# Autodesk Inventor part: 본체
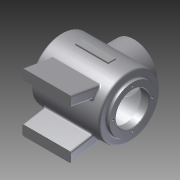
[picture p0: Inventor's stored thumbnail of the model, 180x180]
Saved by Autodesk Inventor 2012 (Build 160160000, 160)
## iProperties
Created: 2015-01
Part Number: 본체
Material: Default
Document SubType Name: Modeling
Designer: Class3-User
Density: 1 g/cm^3
Author: Class3-User
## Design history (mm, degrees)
sketch "스케치1"
  geometry: 1 further point
sketch "스케치2"
  geometry: C1 r 50 at (0, 0); 1 further point
  constraints: 1 centre point, 1 coincident
  dimensions: "d0" = 100 diameter of C1
extrude "돌출1" new body sketch "스케치2" distance "d1" = 112; taper "d2" = 0 deg
sketch "스케치3"
  geometry: C1 r 50 at (0, 0) reference; C2 r 38 at (0, 0)
  constraints: 1 centre point, 1 coincident
  dimensions: "d3" = 76 diameter of C2
extrude "돌출2" join sketch "스케치3" distance "d4" = 5; taper "d5" = 0 deg
sketch "스케치4"
  geometry: C1 r 50 at (0, 0) reference; C2 r 38 at (0, 0)
  constraints: 1 centre point, 1 coincident
  dimensions: "d6" = 76 diameter of C2
extrude "돌출3" join sketch "스케치4" distance "d7" = 5; taper "d8" = 0 deg
node "작업 평면1"
sketch "스케치5"
  geometry: L1 (0, 0)-(5, 0); L2 (5, 0)-(-57, 0); C1 r 38 at (-57, 0)
  constraints: 4 end point, 1 centre point, 1 coincident, 1 collinear, 1 horizontal
  dimensions: "d10" = 5 distance of L1.start L1.end; "d11" = 62 distance of L1.end L2.end; "d12" = 76 diameter of C1
extrude "돌출4" join sketch "스케치5" distance "d13" = 50; taper "d14" = 0 deg
sketch "스케치6"
  geometry: C1 r 38 at (0, 0) reference; C2 r 27 at (0, 0)
  constraints: 1 centre point, 1 coincident
  dimensions: "d15" = 54 diameter of C2
extrude "돌출5" cut sketch "스케치6" stored distance "d16" = 99; taper "d17" = 0 deg
node "작업 평면2"
sketch "스케치7"
  geometry: C1 r 45 at (0, 0); 1 further point
  constraints: 1 centre point, 1 coincident
  dimensions: "d19" = 90 diameter of C1
extrude "돌출6" cut sketch "스케치7" distance "d20" = 97; taper "d21" = 0 deg
sketch "스케치8"
  geometry: C1 r 38 at (0, 0) reference; C2 r 27 at (0, 0); 1 further point
  constraints: 1 centre point, 1 coincident
  dimensions: "d22" = 54 diameter of C2
extrude "돌출7" cut sketch "스케치8" distance "d23" = 50; taper "d24" = 0 deg
sketch "스케치9" dims "d25" = 64
  geometry: L1 (0, 32)-(0, 0); C1 r 38 at (0, 0) reference; C2 r 2 at (0, 32); 1 further point
  constraints: 2 end point, 1 centre point, 1 coincident, 1 vertical, 1 vertical alignment, 2 other
  dimensions: "d26" = 4 diameter of C2
hole "구멍1" sketch "스케치9" at (0, 32) diameter "d27" = 3.459; stored, may be unused: countersink angle "d31" = 82 deg, drill point angle "d33" = 118 deg; dims "d28" = 8, "d29" = 3.023, "d30" = 2, "d32" = 10
sketch "스케치10" dims "d37" = 64
  geometry: L1 (0, 0)-(0, 32); C1 r 38 at (0, 0) reference; C2 r 2 at (0, 32)
  constraints: 2 end point, 1 centre point, 1 coincident, 1 vertical, 1 vertical alignment, 2 other
  dimensions: "d38" = 4 diameter of C2
hole "구멍2" sketch "스케치10" at (0, 32) diameter "d39" = 3.459; stored, may be unused: countersink angle "d43" = 82 deg, drill point angle "d45" = 118 deg; dims "d40" = 8, "d41" = 3.023, "d42" = 2, "d44" = 10
sketch "스케치11" dims "d49" = 64
  geometry: L1 (0, 0)-(0, 32); C1 r 38 at (0, 0) reference; C2 r 2 at (0, 32)
  constraints: 2 end point, 1 centre point, 1 coincident, 1 vertical, 1 vertical alignment, 2 other
  dimensions: "d50" = 4 diameter of C2
hole "구멍3" sketch "스케치11" at (0, 32) diameter "d51" = 3.459; stored, may be unused: countersink angle "d55" = 82 deg, drill point angle "d57" = 118 deg; dims "d52" = 8, "d53" = 3.023, "d54" = 2, "d56" = 10
node "작업 평면3"
sketch "스케치12"
  geometry: L1 (0, 0)-(0, -80); L2 (0, -80)-(-48, -80); L3 (-48, -80)-(-38.973, -28.807) reference; L4 (-38.973, -28.807)-(-24.238, -39.957) reference; L5 (-24.238, -39.957)-(-31.298, -80) reference
  constraints: 10 end point, 1 parallel, 1 perpendicular, 1 point on line, 1 vertical, 3 other
  dimensions: "d62" = 80 distance of L1.start L1.end
extrude "돌출8" join sketch "스케치12" distance "d66" = 80; taper "d67" = 0 deg
fillet "모깎기1" dims "d68" = 3
fillet "모깎기2" dims "d69" = 3
chamfer "모따기1" distance "d70" = 1; stored, may be unused: second distance "d71" = 2, angle "d72" = 45 deg
fillet "모깎기3" dims "d73" = 3
fillet "모깎기4" dims "d74" = 3
sketch "스케치13"
  geometry: 1 further point
node "작업 평면4"
sketch "스케치14"
  geometry: L1 (0, 0)-(56, 0); L2 (56, 0)-(56, 6); L3 (56, 6)-(29, 6); L4 (29, 6)-(29, -6); L5 (29, -6)-(83, -6); L6 (83, -6)-(83, 6); L7 (83, 6)-(56, 6)
  constraints: 14 end point, 3 perpendicular, 2 parallel, 1 horizontal
  dimensions: "d76" = 56 distance of L1.start L1.end; "d77" = 6 distance of L1.end L2.end; "d78" = 27 distance of L2.end L3.end; "d79" = 12 distance of L3.end L4.end; "d80" = 54 distance of L4.end L5.end; "d81" = 12 distance of L5.end L6.end
extrude "돌출9" join sketch "스케치14" distance "d82" = 4; taper "d83" = 0 deg
sketch "스케치15"
  geometry: L1 (-52, 6)-(-52, -6) reference; L2 (-49.639, 6)-(-52, 6) reference; L3 (-52, -6)-(-49.639, -6) reference; C1 r 28 at (0, 0) reference; A1 r 50 centre (0, 0) between (-49.639, 6) and (-49.639, -6) reference
  constraints: 6 end point, 2 horizontal, 2 point on circle, 1 centre point, 1 coincident, 1 parallel, 1 vertical, 5 other
extrude "돌출10" cut sketch "스케치15" distance "d88" = 99; taper "d89" = 0 deg
node "작업 평면5"
sketch "스케치16"
  geometry: L1 (0, 0)-(56, 0); L2 (56, 0)-(56, -6); L3 (56, -6)-(29, -6); L4 (29, -6)-(29, 6); L5 (29, 6)-(83, 6); L6 (83, 6)-(83, -6); L7 (83, -6)-(56, -6)
  constraints: 14 end point, 3 perpendicular, 2 parallel, 1 horizontal
  dimensions: "d91" = 56 distance of L1.start L1.end; "d92" = 6 distance of L1.end L2.end; "d93" = 27 distance of L2.end L3.end; "d94" = 12 distance of L3.end L4.end; "d95" = 54 distance of L4.end L5.end; "d96" = 12 distance of L5.end L6.end
extrude "돌출11" join sketch "스케치16" distance "d97" = 4; taper "d98" = 0 deg
node "솔리드1"
pattern_circular "원형 패턴1" dims angle "d35" = 360 deg
pattern_circular "원형 패턴2" dims angle "d47" = 360 deg
pattern_circular "원형 패턴3" dims angle "d59" = 360 deg
mirror "대칭1"
other parameters: "d9" = 62, "d18" = -7, "d61" = -21, "d75" = -52, "d90" = 52
